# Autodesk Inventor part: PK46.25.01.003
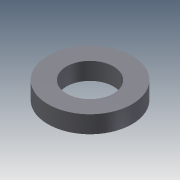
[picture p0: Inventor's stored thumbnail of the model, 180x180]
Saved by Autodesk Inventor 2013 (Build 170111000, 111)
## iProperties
Created: 2005-04
Part Number: PK46.25.01.003
Material: Steel, Mild
Document SubType Name: Modeling
Designer: salex
Manufacturer: Standard
Standards Organization: Custom
Density: 7.86 g/cm^3
Author: salex
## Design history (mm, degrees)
sketch "Эскиз1"
  geometry: C1 r 47.5 at (0, 0); C2 r 85 at (0, 0)
  constraints: 2 centre point, 1 concentric, 1 other
  dimensions: "d0" = 95 diameter of C1; "d1" = 170 diameter of C2
extrude "Выдавливание1" new body sketch "Эскиз1" distance "d2" = 35; taper "d3" = 0 deg
body "Solid1"
